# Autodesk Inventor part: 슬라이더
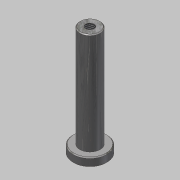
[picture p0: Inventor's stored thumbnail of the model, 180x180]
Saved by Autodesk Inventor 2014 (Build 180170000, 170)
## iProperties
Created: 2016-02
Part Number: 슬라이더
Material: 스테인리스강
Document SubType Name: Modeling
Designer: mduedu
Density: 8.08 g/cm^3
Appearance: 반광택
Mass: 65.4431 g
Surface Area: 33.4413 cm^2
Volume: 8.0994 cm^3
Author: mduedu
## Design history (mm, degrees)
sketch "스케치1"
  geometry: C1 r 10 at (0, 0); 1 further point
  constraints: 1 centre point, 1 coincident
  dimensions: "d0" = 20 diameter of C1
extrude "돌출1" new body sketch "스케치1" distance "d1" = 5; taper "d2" = 0 deg
sketch "스케치2"
  geometry: C1 r 6 at (0, 0); 1 further point
  constraints: 1 centre point, 1 coincident
  dimensions: "d3" = 12 diameter of C1
extrude "돌출2" join sketch "스케치2" distance "d4" = 60; taper "d5" = 0 deg
chamfer "모따기1" distance "d6" = 0.5; stored, may be unused: second distance "d7" = 2, angle "d8" = 45 deg
hole "구멍1" diameter "d11" = 4.917; stored, may be unused: countersink angle "d15" = 90 deg, drill point angle "d17" = 118 deg; dims "d9" = 10, "d10" = 10, "d12" = 10, "d13" = 4, "d14" = 2, "d16" = 12
chamfer "모따기2" distance "d18" = 0.5; stored, may be unused: second distance "d19" = 2, angle "d20" = 45 deg
node "솔리드1"
